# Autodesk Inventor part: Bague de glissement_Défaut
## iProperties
Shininess: 64.0
Length Units: 11269
Angle Units: 11279
Time Units: 11290
Mass Units: 11283
Length Display Precision: 3
Angle Display Precision: 2
Compacted: True
Part Number: Bague de glissement_Défaut
Document SubType Name: Modeling
Created: 2006-01
Material: Par défaut
Designer: riri
Density: 0.0
Volumn: 0.0
Area: 0.0
PropertySet Name: Model Information
Control State: 0
Master: False
Checked Out: False
Author: riri
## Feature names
1. Base1
